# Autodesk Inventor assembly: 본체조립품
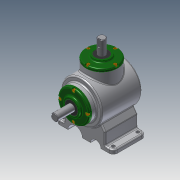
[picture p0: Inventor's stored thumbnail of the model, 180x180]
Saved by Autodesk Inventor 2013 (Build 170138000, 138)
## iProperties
Created: 2018-08
Part Number: 본체조립품
Document SubType Name: Assembly
Designer: Administrator
Author: Administrator
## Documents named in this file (14)
- C:\Users\Administrator\Desktop\480808V1008\본체조립품.iam
- C:\Users\Administrator\Desktop\480808V1008\본체.ipt
- C:\Users\Administrator\Desktop\480808V1008\메인 베벨기어.ipt
- C:\Users\Administrator\Desktop\480808V1008\메인 축.ipt
- 메인 축.ipt
- C:\Users\Administrator\Desktop\480808V1008\베어링 6203.ipt
- C:\Users\Administrator\Desktop\480808V1008\볼트 M4.ipt
- C:\Users\Administrator\Desktop\480808V1008\서브 베벨기어.ipt
- C:\Users\Administrator\Desktop\480808V1008\서브 축.ipt
- 서브 축.ipt
- C:\Users\Administrator\Desktop\480808V1008\오일실 17 32 8.ipt
- C:\Users\Administrator\Desktop\480808V1008\커버.ipt
- C:\Users\Administrator\Desktop\480808V1008\키 4x4.ipt
- C:\Users\Administrator\Desktop\480808V1008\키 5x5.ipt
